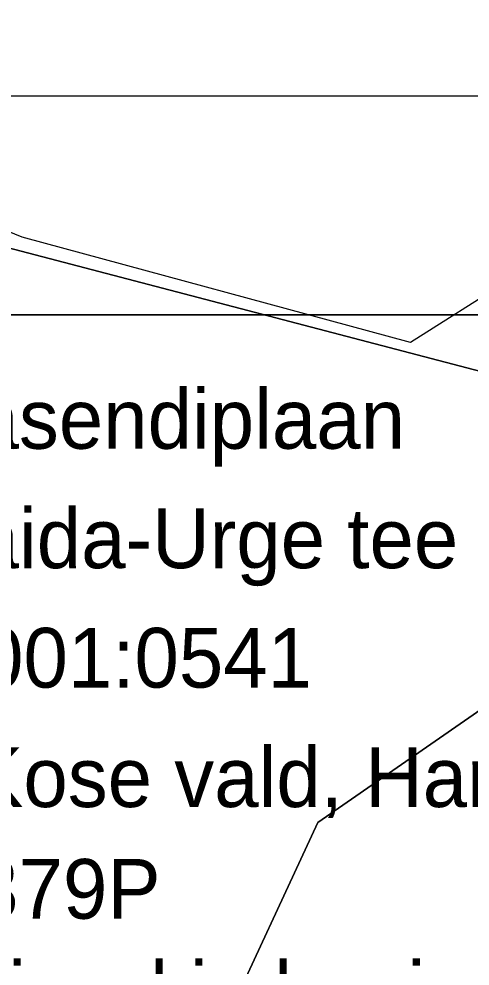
# Model space of a CAD drawing. Extents: x 554947 to 555436, y 6564938 to 6565792.
# Drawn here: x 555064.02 to 555086.69, y 6565611.19 to 6565658.77 of the extents above; entities that cross this region are included whole.
import ezdxf

# ---------------------------------------------------------------- set-up
doc = ezdxf.new("R2010")
doc.units = 0
for name, color, linetype in [('PIIR', 7, 'Continuous'), ('PR_SIDE', 7, 'Continuous'), ('VORMISTUS_2', 7, 'Continuous')]:
    doc.layers.add(name, color=color, linetype=linetype)

msp = doc.modelspace()

# ---------------------------------------------------------------- linework, layer by layer
at = {"layer": 'PIIR'}
for points in [[(555140.201, 6565654.913), (555137.2, 6565645.72), (555136.5, 6565633.07), (555130.73, 6565621.32), (555129.77, 6565611.2), (555114.24, 6565634), (555063.43, 6565647.29), (555047.17, 6565654.02), (555045.31, 6565654.913)], [(555144.16, 6565410.6), (555124.27, 6565454.45), (555113.82, 6565475.68), (555076.76, 6565542.38), (555065.78, 6565566.7), (555060.42, 6565583.26), (555057.22, 6565600.73), (555056.61, 6565622.91), (555063.43, 6565647.29), (555114.24, 6565634), (555129.77, 6565611.2), (555130.73, 6565621.32), (555138.66, 6565615.26), (555160.12, 6565598.86), (555193.24, 6565604.68), (555193.7, 6565602.7), (555225.47, 6565605.89), (555234.35, 6565605.6), (555251.24, 6565598.48), (555330.71, 6565538.85), (555343.81, 6565536.56), (555350.68, 6565540.44), (555361.56, 6565549.57), (555393.069, 6565582.099)], [(555171.91, 6565394.64), (555091.74, 6565551.94), (555075.34, 6565593.24), (555074.13, 6565607.82), (555079.04, 6565618.4), (555093.56, 6565628.47), (555109.96, 6565624.83), (555116.17, 6565610.5), (555099.5, 6565594.91), (555105.26, 6565587.71), (555119.63, 6565564.84), (555126.35, 6565558.74), (555131.01, 6565550.06), (555139.64, 6565543.1), (555141.68, 6565537.52), (555139.26, 6565529.51), (555139.49, 6565523.98), (555140.65, 6565513.25), (555142.13, 6565499.56), (555141.53, 6565491.02), (555141.65, 6565472.71), (555143.93, 6565463.6), (555153.01, 6565448.47), (555207.22, 6565406.57)], [(555393.069, 6565560.972), (555353.12, 6565523.87), (555343.14, 6565512.46), (555302.6, 6565539.71), (555242.37, 6565583.94), (555179.42, 6565586.32), (555138.98, 6565580.6), (555121.18, 6565602.26), (555116.17, 6565610.5), (555109.96, 6565624.83), (555093.56, 6565628.47), (555079.04, 6565618.4), (555074.13, 6565607.82), (555075.34, 6565593.24), (555091.74, 6565551.94), (555171.91, 6565394.64), (555191.35, 6565341.19), (555195.08, 6565294.61), (555195.28, 6565271.63), (555191.64, 6565237.48)]]:
    msp.add_lwpolyline(points, dxfattribs=at)
at = {"layer": 'PR_SIDE'}
msp.add_lwpolyline([(555093.45, 6565648.677), (555083.692, 6565642.526), (555064.179, 6565647.804), (555056.079, 6565651.133), (555046.326, 6565658.494), (555043.563, 6565658.774)], dxfattribs=at)
at = {"layer": 'VORMISTUS_2'}
for points in [[(554999.363, 6565654.913), (555209.363, 6565654.913), (555209.363, 6565357.913), (554999.363, 6565357.913)], [(555009.363, 6565368.913), (555199.363, 6565368.913), (555199.363, 6565643.913), (555009.363, 6565643.913)], [(555009.363, 6565643.913), (555199.363, 6565643.913), (555199.363, 6565368.913), (555009.363, 6565368.913)]]:
    msp.add_lwpolyline(points, close=True, dxfattribs=at)

# ---------------------------------------------------------------- texts
for s, p in [('Isikliku kasutusõiguse asendiplaan', (555021.874, 6565637.182)), ('Kinnistu nimi: 11202 Vaida-Urge tee', (555021.874, 6565631.182)), ('Katastritunnus: 33701:001:0541', (555021.874, 6565625.182)), ('Asukoht: Tuhala küla, Kose vald, Harju maakond', (555021.874, 6565619.182))]:
    msp.add_text(s, height=3, dxfattribs=at).set_placement(p)
for s, p in [('Kirjanurk OÜ töö nr 10379P', (555021.859, 6565613.572)), ('Kose vald, Tuhala ja Otiveski elurajooni sideühendus', (555021.782, 6565608.425))]:
    msp.add_text(s, height=3, rotation=360, dxfattribs=at).set_placement(p)

doc.saveas('drawing.dxf')
